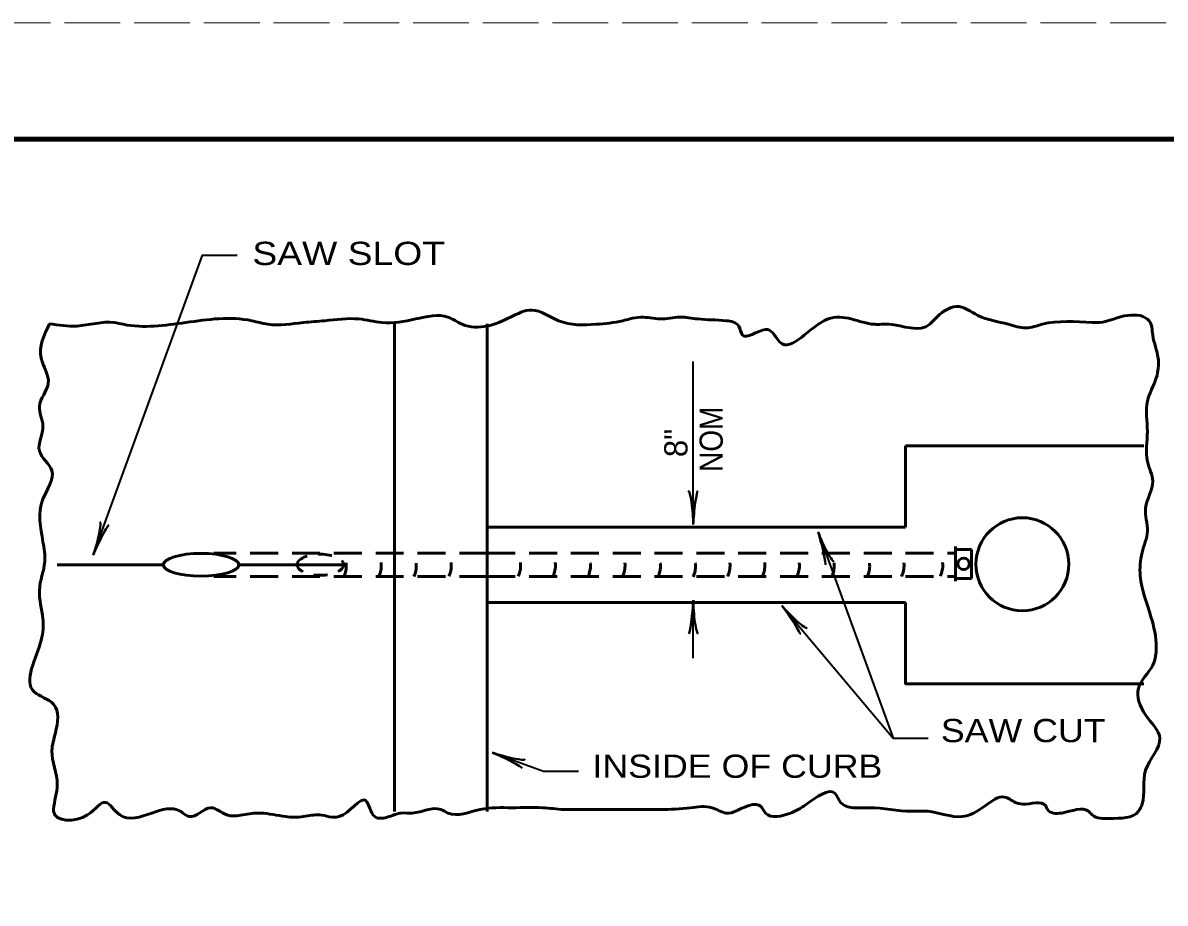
# Model space of a CAD drawing. Extents: x -58 to 622, y -372 to 68.
# Drawn here: x 118 to 216.3, y -7.8 to 68 of the extents above; entities that cross this region are included whole.
import ezdxf

# ---------------------------------------------------------------- set-up
doc = ezdxf.new("R2010")
doc.units = 0
doc.header["$LTSCALE"] = 0.8
for name, pattern in [('LONG_DASHED', [7.5, 6, -1.5]), ('MEDIUM_DASHED', [4.5, 3, -1.5]), ('SHORT_DASHED', [2.7, 1.5, -1.2])]:
    doc.linetypes.add(name, pattern=pattern)
doc.layers.add('1', color=7, linetype='Continuous', lineweight=35)
doc.layers.add('61', color=7, linetype='Continuous', lineweight=35)

msp = doc.modelspace()

# ---------------------------------------------------------------- linework, layer by layer
at = {"layer": '1', "lineweight": 53}
for p, q in [((149.9592, 42.0949), (149.9592, 0.0949)), ((157.9592, 42.0949), (157.9592, 0.0949)), ((193.9592, 24.5949), (193.9592, 31.5949)), ((214.4592, 31.5949), (193.9592, 31.5949)), ((157.9592, 24.5949), (193.9592, 24.5949)), ((198.2224, 22.6517), (199.6428, 22.6517)), ((198.2608, 22.9204), (198.2608, 19.9204)), ((199.6428, 22.6517), (199.6428, 20.1517)), ((130.0465, 21.3519), (120.9388, 21.3519)), ((136.553, 21.3327), (145.593, 21.3327)), ((198.2224, 20.1517), (199.6428, 20.1517)), ((157.9592, 18.0949), (193.9592, 18.0949))]:
    msp.add_line(p, q, dxfattribs=at)
at = {"layer": '1'}
for p, q in [((175.6863, 24.8259), (175.6863, 38.8405)), ((186.4273, 24.1614), (192.8893, 6.4073)), ((175.6863, 13.2918), (175.6863, 18.2751))]:
    msp.add_line(p, q, dxfattribs=at)
at = {"layer": '1', "linetype": 'MEDIUM_DASHED', "lineweight": 53}
for p, q in [((157.9592, 22.3449), (134.4213, 22.3449)), ((157.9592, 22.3449), (198.2608, 22.3449)), ((157.9592, 20.3449), (134.4213, 20.3449)), ((157.9592, 20.3449), (198.2608, 20.3449))]:
    msp.add_line(p, q, dxfattribs=at)
at = {"layer": '1'}
for points in [[(124.0472, 22.1841), (133.4392, 47.9881), (136.4392, 47.9881)], [(183.3132, 17.8196), (192.8893, 6.4073), (195.8893, 6.4073)], [(158.3773, 5.1835), (162.7943, 3.5757), (165.7943, 3.5757)]]:
    msp.add_lwpolyline(points, dxfattribs=at)
at = {"layer": '1', "lineweight": 53}
msp.add_lwpolyline([(193.9592, 18.0949), (193.9592, 11.0949), (214.4592, 11.0949)], dxfattribs=at)
for centre, radius in [((204.0092, 21.3921), 4), ((198.9517, 21.4233), 0.5)]:
    msp.add_circle(centre, radius, dxfattribs=at)
at = {"layer": '1', "linetype": 'SHORT_DASHED', "lineweight": 53}
for centre in [(143.6508, 21.2645), (146.6639, 21.2838), (149.6771, 21.2454), (152.6904, 21.2838), (158.6592, 21.2838), (161.6532, 21.2838), (164.6664, 21.2454), (167.6411, 21.2646), (170.6927, 21.2454), (173.7059, 21.2262), (176.6807, 21.2646), (179.6747, 21.2838), (182.6495, 21.2646), (185.6435, 21.2455), (188.6951, 21.2455), (191.6509, 21.2646), (194.9841, 21.2897)]:
    msp.add_arc(centre, 2.1707, 334.94384, 29.7373, dxfattribs=at)
at = {"layer": '1', "lineweight": 40}
for centre, major_axis, ratio, start_param, end_param in [((175.41, 25.9171), (0.1562, -1.7857), 0.122415, 0.8963533, 3.1415927), ((175.8979, 25.9464), (0.1757, 1.7565), 0.07063, 6.2823074, 8.5597026), ((124.1608, 23.304), (-0.464, -1.7314), 0.122415, 0.8963533, 3.1415927), ((124.6293, 23.1646), (0.7658, 1.5904), 0.07063, 6.2823074, 8.5597026), ((186.6117, 23.0361), (-0.4357, 1.7106), 0.07063, 3.1407148, 5.41811), ((186.6117, 23.0361), (-0.4357, 1.7106), 0.07063, 3.1407148, 5.41811), ((187.0602, 23.2305), (-0.7575, 1.6246), 0.122415, 0.8963533, 3.1415927), ((187.0602, 23.2305), (-0.7575, 1.6246), 0.122415, 0.8963533, 3.1415927), ((175.4747, 17.1546), (-0.1757, -1.7565), 0.07063, 6.2823074, 8.5597026), ((175.9626, 17.1839), (-0.1562, 1.7857), 0.122415, 0.8963533, 3.1415927), ((183.8713, 16.8252), (0.9945, -1.4584), 0.07063, 6.2823074, 8.5597026), ((184.2262, 17.1613), (-1.2674, 1.2675), 0.122415, 0.8963533, 3.1415927), ((159.3578, 4.6014), (1.5904, -0.7658), 0.07063, 6.2823074, 8.5597026), ((159.4971, 5.0699), (-1.7314, 0.464), 0.122415, 0.8963533, 3.1415927)]:
    msp.add_ellipse(centre, major_axis=major_axis, ratio=ratio, start_param=start_param, end_param=end_param, dxfattribs=at)
at = {"layer": '1', "lineweight": 53}
msp.add_ellipse((133.3222, 21.3449), major_axis=(-3.25, 0), ratio=0.300371, dxfattribs=at)
at = {"layer": '1', "linetype": 'SHORT_DASHED', "lineweight": 53}
msp.add_ellipse((143.5932, 21.3449), major_axis=(-2, 0), ratio=0.452986, dxfattribs=at)
at = {"layer": '1', "lineweight": 53}
for points in [[(120.2778, 42.0949), (122.6377, 41.8891), (125.8622, 42.1962), (126.6299, 42.0427), (132.0042, 42.1962), (137.6854, 42.3498), (139.0673, 42.0427), (142.1383, 42.1962), (143.9808, 42.3498), (146.8982, 42.5033), (148.8944, 42.1962), (151.8118, 42.5033), (154.5757, 42.6568), (155.8041, 42.0427), (157.9537, 41.8891), (159.9498, 42.6568), (161.7924, 43.2711), (164.0957, 42.3498), (167.3202, 42.0427), (169.6234, 42.3498), (170.2376, 42.5033), (171.1588, 42.6568), (172.8479, 42.5033), (174.5369, 42.6568), (176.0724, 42.5033), (178.5292, 42.3498), (179.604, 41.8891), (179.9111, 41.1214), (181.9073, 41.582), (182.0607, 41.582), (183.1356, 40.5072), (187.2814, 42.5033), (189.2775, 42.5033), (191.2737, 42.0427), (192.502, 42.0427), (196.0337, 42.0427), (196.1872, 42.1962), (197.4156, 43.2711), (198.3368, 43.5782), (200.1794, 42.8104), (202.7897, 42.0427), (204.3252, 41.7356), (205.7072, 42.0427), (210.0065, 42.1962), (210.6207, 42.1962), (213.0774, 42.8104), (214.1523, 42.8104)], [(214.1523, 42.8104), (214.92, 42.3498), (215.2272, 41.1214), (215.6877, 39.1253), (215.5342, 37.4363), (214.7665, 35.4401), (214.7665, 32.8298), (214.7665, 30.2195), (215.2272, 28.5304), (214.6129, 26.2272), (214.7665, 24.2311), (214.3058, 22.3885), (214.1523, 20.3924), (215.0736, 16.8608), (215.5342, 14.2505), (215.2272, 12.715), (213.9988, 10.7189), (214.6129, 8.4157), (215.8413, 6.4196), (214.6129, 3.6557), (214.3058, 0.7382), (213.9988, 0.1241), (211.542, -0.4901), (210.0065, -0.183), (209.6994, 0.1241), (207.3962, -0.0295), (206.1678, 0.2777), (206.0143, 0.5847), (204.0182, 0.7382), (203.4039, 0.8918), (202.4827, 1.3525), (200.7936, 0.5847), (198.7975, -0.3366), (195.8801, 0.1241), (194.4982, 0.1241), (190.813, 0.4312), (189.4311, 0.4312), (188.3562, 0.8918), (187.8956, 1.6596), (185.4388, 0.7382), (184.9782, 0.4312), (184.0569, -0.0295), (181.9073, -0.0295), (181.4466, 0.5847), (180.3717, 0.5847), (178.5292, -0.0295), (177.3007, 0.4312), (175.4582, 0.4312), (172.8479, 0.2777), (171.1588, 0.2777), (168.0879, 0.2777), (166.0917, 0.2777), (164.5563, 0.2777), (162.7138, 0.4312), (160.1034, 0.4312), (157.3396, 0.2777), (154.5757, -0.0295), (153.9615, 0.2777), (151.5048, -0.0295), (150.5834, -0.0295), (149.5086, -0.3366), (148.2802, -0.3366), (147.5125, 1.0453), (145.2092, -0.3366), (143.5203, -0.183), (142.1383, -0.3366), (140.6028, -0.3366), (138.4532, -0.0295), (136.9177, -0.183), (135.5358, -0.183), (134.1538, 0.4312), (132.3113, -0.3366), (131.5435, 0.1241), (129.0867, -0.0295), (126.3228, -0.183), (125.0945, 0.8918), (123.559, -0.183), (120.6416, 0.1241), (120.6416, 0.2777), (120.9487, 2.4273), (120.488, 5.3447), (120.7952, 6.8802), (120.6416, 9.3369), (118.9526, 10.4117), (119.5667, 14.8647), (119.7203, 16.7072), (119.4132, 19.164), (119.8738, 21.6208), (119.7203, 23.3098), (119.7203, 26.995), (120.488, 29.4518), (119.4132, 31.1408), (119.7203, 33.2904), (119.4132, 34.9795), (120.1809, 36.9756), (119.5667, 39.1253), (120.2778, 42.0949)]]:
    msp.add_spline(points, degree=3, dxfattribs=at)
at = {"layer": '61', "linetype": 'LONG_DASHED', "lineweight": 13}
msp.add_line((-58.4297, 67.9933), (621.5902, 67.9933), dxfattribs=at)
at = {"layer": '61', "lineweight": 158}
msp.add_lwpolyline([(610.6102, 57.9933), (-28.4297, 57.9933), (-28.4297, -362.0267)], dxfattribs=at)

# ---------------------------------------------------------------- texts
at = {"layer": '1'}
for s, width, p in [('SAW SLOT', 1.2, (137.7387, 47.1477)), ('SAW CUT', 1.15, (196.9911, 6.0724)), ('INSIDE OF CURB', 1.15, (167.0108, 3.0036))]:
    msp.add_text(s, height=2, dxfattribs=dict(at, width=width)).set_placement(p)
at = {"layer": '1', "width": 0.9}
msp.add_text('NOM', height=2, rotation=90, dxfattribs=at).set_placement((178.224, 29.3407))
at = {"layer": '1'}
msp.add_text('8"', height=2, rotation=90, dxfattribs=at).set_placement((175.1846, 30.6096))

doc.saveas('drawing.dxf')
